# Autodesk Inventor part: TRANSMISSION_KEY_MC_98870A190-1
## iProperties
Created: 2008-11
Part Number: TRANSMISSION_KEY_MC_98870A190-1
Document SubType Name: Modeling
Designer: ETUDIANT
Norme de conversion: STEP AP214IS
Nom du fichier: TRANSMISSION_KEY_MC_98870A190.STEP
Préprocesseur: SolidWorks 2008
Postprocesseur: Build: 344a, Release: 11 SP2 - Date: Fri 08/18/2006
Unités envoyées: INCHES
Incertitude: 1e-05
Author: ETUDIANT
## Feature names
1. Base1
